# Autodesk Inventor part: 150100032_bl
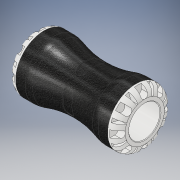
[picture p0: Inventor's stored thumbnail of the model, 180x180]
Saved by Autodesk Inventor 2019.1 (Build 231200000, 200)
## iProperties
Created: 2016-12
Part Number: 150100032_bl
Material: PVC-Piping
Description: PLASSON G-PLASS COUPLING 32X32
Document SubType Name: Modeling
Designer: KIM
Mass: 95.2094 g
Surface Area: 200.83 cm^2
Volume: 68.0067 cm^3
Density: 1.4 g/cm^3
Appearance: White
ILogicFactory: False
Author: KIM
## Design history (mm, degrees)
derived "150100.ipt"
feature "Solid1::150100.ipt" dims "ScaleForDerivedMember" = 10
tag "TaggingFeature1"
body "Solid1"
other parameters: "d2" = 55 [user parameter], "d4" = 2.66667 [user parameter], "d11" = 7.2 [user parameter], "d13" = 7.2 [user parameter], "d14" = 0 [user parameter], "d16" = 360 deg [user parameter], "d18" = 8 deg [user parameter], "d19" = 0.64 [user parameter], "d20" = 8 deg [user parameter], "d21" = 0.64 [user parameter], "d23" = 0 [user parameter], "d25" = 360 deg [user parameter], "d27" = 23.2 [user parameter], "d28" = 8 [user parameter], "d29" = 9.6 [user parameter], "d30" = 9.6 [user parameter], "d31" = 0 [user parameter], "d33" = 0 [user parameter], "d37" = 22.4 [user parameter], "d38" = 0.58 [user parameter], "d43" = 4 [user parameter], "d44" = 32 [user parameter], "d45" = 22.4 [user parameter], "d46" = 46.4 [user parameter], "d47" = 58 [user parameter], "d48" = 112 [user parameter], "d50" = 360 deg [user parameter], "d54" = 0.513 [user parameter], "d_" = 32 [user parameter], "E_" = 58 [user parameter], "H_" = 112 [user parameter], "l_" = 55 [user parameter], "d42" = 58 [user parameter], "d52" = 9 [user parameter]
